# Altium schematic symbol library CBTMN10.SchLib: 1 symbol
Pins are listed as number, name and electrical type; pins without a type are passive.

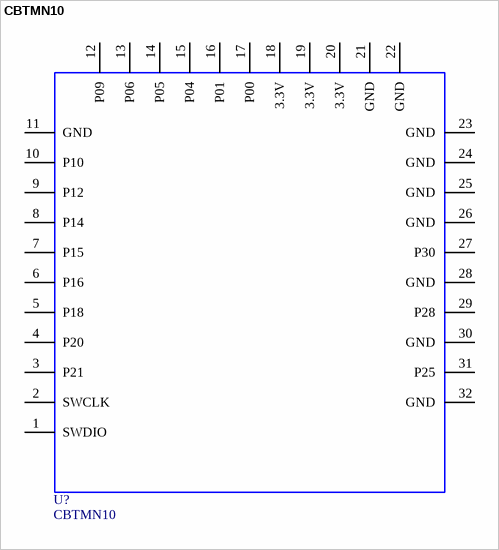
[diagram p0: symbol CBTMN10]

## CBTMN10
designator U?
module CBTMN10
footprint CBTMN10
pins: 1 SWDIO, 2 SWCLK, 3 P21, 4 P20, 5 P18, 6 P16, 7 P15, 8 P14, 9 P12, 10 P10, 11 GND, 12 P09, 13 P06, 14 P05, 15 P04, 16 P01, 17 P00, 18 3.3V, 19 3.3V, 20 3.3V, 21 GND, 22 GND, 23 GND, 24 GND, 25 GND, 26 GND, 27 P30, 28 GND, 29 P28, 30 GND, 31 P25, 32 GND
